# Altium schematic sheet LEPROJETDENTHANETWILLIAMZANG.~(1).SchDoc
size A4
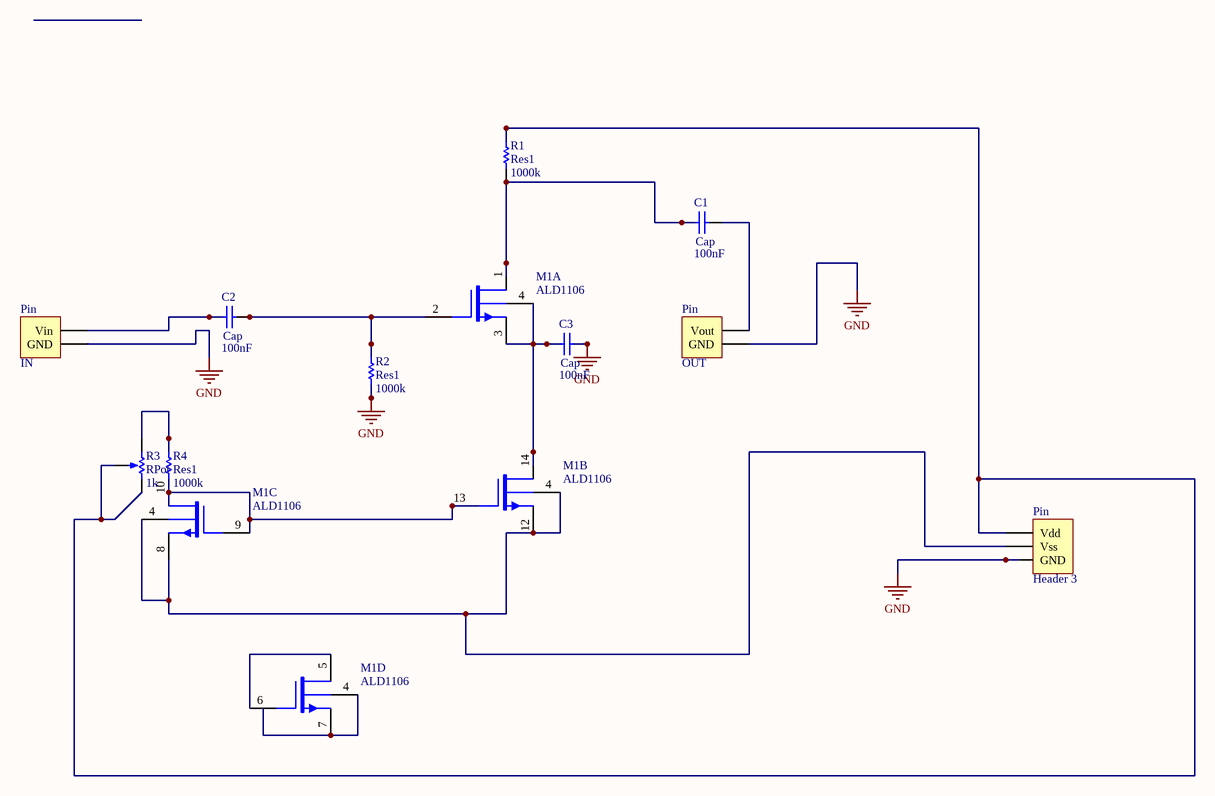
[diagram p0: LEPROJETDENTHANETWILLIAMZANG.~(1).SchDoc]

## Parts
(Parts that share a designator on the sheet are numbered #1, #2 ... from top to bottom, then left to right.)
C1  Cap  value 100nF  [RAD-0.3]
C2  Cap  value 100nF  [RAD-0.3]
C3  Cap  value 100nF  [RAD-0.3]
M1  ALD1106  [DIP-14]  (parts A,B,C,D of 4)
Pin#1  IN  [HDR1X2]
Pin#2  OUT  [HDR1X2]
Pin#3  Header 3  [HDR1X3]
R1  Res1  value 1000k  [AXIAL-0.3]
R2  Res1  value 1000k  [AXIAL-0.3]
R3  RPot  value 1k  [VR5]
R4  Res1  value 1000k  [AXIAL-0.3]

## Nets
GND: C3.2 Pin#1.1(GND) Pin#2.1(GND) Pin#3.3(GND) R2.1
NetC1_1: C1.1 M1.1(DN1) R1.1
NetC1_2: C1.2 Pin#2.2(Vout)
NetC2_1: C2.1 Pin#1.2(Vin)
NetC2_2: C2.2 M1.2(GN1) R2.2
NetC3_1: C3.1 M1.3(SN1) M1.4(V-) M1.14(DN2)
NetM1_4: M1.4(V-) M1.8(SN3) M1.12(SN2) Pin#3.2(Vss)
NetM1_4: M1.4(V-) M1.7(SN4)  [a separate net that carries the same name]
NetM1_5: M1.5(DN4) M1.6(GN4)
NetM1_9: M1.9(GN3) M1.10(DN3) M1.13(GN2) R4.1
NetPin#3_1: Pin#3.1(Vdd) R1.2 R3.2(TAP) R3.3(BOT)
NetR3_1: R3.1(TOP) R4.2

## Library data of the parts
C1-C3 = Cap: Capacitor
M1 = ALD1106: Quad N-channel matched MOSFET array
Pin#1 Pin#2 = Header 2: Header, 2-Pin
Pin#3 = Header 3: Header, 3-Pin
R1 R2 R4 = Res1: Resistor
R3 = RPot: Potentiometer; Sim Note: Enter the Resistance value and the set point into parameter fields.; Set Position: 0.5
